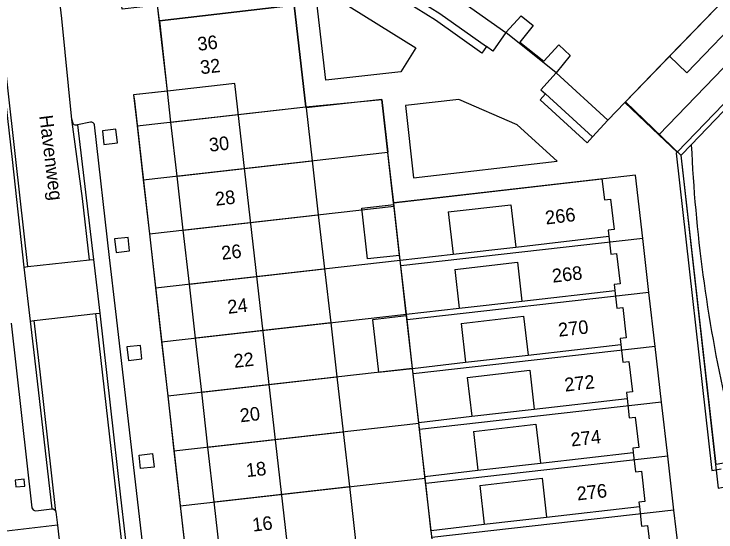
# Model space of a CAD drawing. Extents: x 194485 to 197793, y 468269 to 470822.
# Drawn here: x 194929.3 to 194991.2, y 469505.8 to 469551.5 of the extents above; entities that cross this region are included whole.
import ezdxf

# ---------------------------------------------------------------- set-up
doc = ezdxf.new("R2010")
doc.units = 0
for name, color, linetype in [('BGT begrenzing pand op maaiveld onder overbouw', 7, 'Continuous'), ('BGT grensvlak gebouwinstallatie plus 1', 7, 'Continuous'), ('BGT grensvlak onbegroeid terreindeel', 7, 'Continuous'), ('BGT grensvlak pand deel overbouw', 7, 'Continuous'), ('BGT grensvlak pand min 1', 7, 'Continuous'), ('BGT grensvlak pand op maaiveld', 7, 'Continuous'), ('BGT grensvlak pand op maaiveld LR', 7, 'Continuous'), ('BGT grensvlak scheiding', 7, 'Continuous'), ('BGT grensvlak wegdeel', 7, 'Continuous'), ('BGT lijnelement scheiding muur', 7, 'Continuous'), ('BGT tekst huisnummerreeks', 7, 'Continuous'), ('BGT tekst huisnummerreeks min 1', 7, 'Continuous'), ('BGT tekst openbare ruimte label weg', 7, 'Continuous'), ('GEM grensvlak WOZ_BRK percelen', 7, 'Continuous')]:
    doc.layers.add(name, color=color, linetype=linetype)

msp = doc.modelspace()

# ---------------------------------------------------------------- linework, layer by layer
at = {"layer": 'BGT begrenzing pand op maaiveld onder overbouw'}
msp.add_line((194987.109, 469547.829), (194992.078, 469552.978), dxfattribs=at)
msp.add_lwpolyline([(194972.663, 469549.909), (194974.005, 469551.384), (194975.072, 469550.524), (194973.905, 469549.076), (194976.016, 469547.376), (194977.329, 469548.818), (194978.342, 469547.895), (194977.091, 469546.343)], dxfattribs=at)
at = {"layer": 'BGT grensvlak gebouwinstallatie plus 1'}
for p, q in [((194959.954, 469534.412), (194962.773, 469534.723)), ((194960.447, 469529.925), (194959.954, 469534.412)), ((194963.286, 469530.238), (194960.447, 469529.925)), ((194963.896, 469524.895), (194960.909, 469524.553)), ((194960.909, 469524.553), (194961.439, 469519.927)), ((194961.439, 469519.927), (194964.426, 469520.269))]:
    msp.add_line(p, q, dxfattribs=at)
at = {"layer": 'BGT grensvlak onbegroeid terreindeel'}
msp.add_line((194980.312, 469540.703), (194976.144, 469544.5), dxfattribs=at)
msp.add_lwpolyline([(194962.56, 469554.267), (194966.831, 469551.598), (194970.958, 469548.667)], dxfattribs=at)
at = {"layer": 'BGT grensvlak pand deel overbouw'}
msp.add_line((194977.091, 469546.343), (194972.663, 469549.909), dxfattribs=at)
msp.add_lwpolyline([(194992.415, 469553.349), (194993.948, 469551.885), (194988.626, 469546.362), (194987.109, 469547.829)], dxfattribs=at)
at = {"layer": 'BGT grensvlak pand min 1'}
for points in [[(195136.748, 469494.684), (194989.988, 469465.668), (194991.149, 469459.781), (194987.304, 469459.017), (194987.908, 469455.979), (194958.837, 469450.201), (194954.733, 469470.846), (194957.233, 469471.136), (194948.757, 469545.418), (194942.798, 469544.743), (194941.933, 469552.333), (194938.82, 469551.976), (194935.239, 469583.018)], [(194992.078, 469552.978), (194983.207, 469543.786), (194988.084, 469539.079), (194991.402, 469509.689), (195033.444, 469518.043), (195038.067, 469534.581), (195024.346, 469538.411), (195028.4, 469552.907), (195043.72, 469548.616), (195044.259, 469550.568), (195051.101, 469548.618), (195057.258, 469546.789), (195062.48, 469545.169), (195068.699, 469543.142), (195074.87, 469540.905), (195079.968, 469538.994), (195086.152, 469536.574), (195092.257, 469534.001), (195097.233, 469531.758)]]:
    msp.add_lwpolyline(points, dxfattribs=at)
at = {"layer": 'BGT grensvlak pand op maaiveld'}
for p, q in [((194967.941, 469553.263), (194972.663, 469549.909)), ((194942.8, 469544.724), (194942.093, 469550.932)), ((194983.154, 469543.731), (194987.109, 469547.829)), ((194977.091, 469546.343), (194981.659, 469542.182)), ((194943.109, 469542.014), (194942.8, 469544.724)), ((194955.027, 469543.363), (194955.038, 469543.265)), ((194955.038, 469543.265), (194955.571, 469538.594)), ((194981.659, 469542.182), (194983.154, 469543.731)), ((194943.653, 469537.245), (194943.109, 469542.014)), ((194955.571, 469538.594), (194956.116, 469533.825)), ((194944.196, 469532.476), (194943.653, 469537.245)), ((194962.773, 469534.723), (194962.756, 469534.874)), ((194963.286, 469530.238), (194962.773, 469534.723)), ((194967.579, 469534.07), (194973.102, 469534.706)), ((194973.102, 469534.706), (194973.528, 469530.98)), ((194967.579, 469534.07), (194968.007, 469530.345)), ((194956.116, 469533.825), (194956.661, 469529.056)), ((194944.74, 469527.707), (194944.196, 469532.476)), ((194968.007, 469530.345), (194973.528, 469530.98)), ((194963.335, 469529.807), (194963.286, 469530.238)), ((194963.88, 469525.038), (194963.335, 469529.807)), ((194968.162, 469529.003), (194973.681, 469529.639)), ((194973.681, 469529.639), (194974.073, 469526.211)), ((194956.661, 469529.056), (194957.206, 469524.287)), ((194968.162, 469529.003), (194968.556, 469525.576)), ((194945.284, 469522.938), (194944.74, 469527.707)), ((194968.556, 469525.576), (194974.073, 469526.211)), ((194963.896, 469524.895), (194963.88, 469525.038)), ((194964.426, 469520.269), (194963.896, 469524.895)), ((194968.71, 469524.235), (194974.227, 469524.87)), ((194974.227, 469524.87), (194974.619, 469521.442)), ((194957.206, 469524.287), (194957.75, 469519.518)), ((194968.71, 469524.235), (194969.105, 469520.808)), ((194945.827, 469518.168), (194945.284, 469522.938)), ((194969.105, 469520.808), (194974.619, 469521.442)), ((194964.971, 469515.5), (194964.426, 469520.269)), ((194969.259, 469519.466), (194974.772, 469520.101)), ((194974.772, 469520.101), (194975.164, 469516.673)), ((194957.75, 469519.518), (194958.304, 469514.674)), ((194969.259, 469519.466), (194969.654, 469516.039)), ((194946.379, 469513.325), (194945.827, 469518.168)), ((194969.654, 469516.039), (194975.164, 469516.673)), ((194965.516, 469510.731), (194964.971, 469515.5)), ((194969.808, 469514.698), (194975.317, 469515.332)), ((194975.317, 469515.332), (194975.709, 469511.904)), ((194958.304, 469514.674), (194958.857, 469509.831)), ((194969.808, 469514.698), (194970.202, 469511.271)), ((194946.931, 469508.481), (194946.379, 469513.325)), ((194970.202, 469511.271), (194975.709, 469511.904)), ((194966.061, 469505.962), (194965.516, 469510.731)), ((194970.357, 469509.929), (194975.862, 469510.563)), ((194975.862, 469510.563), (194976.254, 469507.135)), ((194958.857, 469509.831), (194959.402, 469505.062)), ((194970.357, 469509.929), (194970.751, 469506.502)), ((194947.475, 469503.712), (194946.931, 469508.481)), ((194970.751, 469506.502), (194976.254, 469507.135)), ((194966.606, 469501.193), (194966.061, 469505.962))]:
    msp.add_line(p, q, dxfattribs=at)
for points in [[(194942.093, 469550.932), (194953.991, 469552.32), (194955.027, 469543.363)], [(194962.756, 469534.874), (194981.116, 469536.987), (194981.355, 469535.138), (194981.902, 469535.199), (194982.201, 469532.517), (194981.674, 469532.458), (194981.734, 469531.924)], [(194981.734, 469531.924), (194981.909, 469530.351), (194982.436, 469530.41), (194982.739, 469527.726), (194982.212, 469527.667), (194982.271, 469527.154)], [(194982.271, 469527.154), (194982.451, 469525.583), (194982.978, 469525.642), (194983.278, 469522.962), (194982.751, 469522.902), (194982.81, 469522.385)], [(194982.81, 469522.385), (194982.99, 469520.818), (194983.517, 469520.878), (194983.823, 469518.195), (194983.296, 469518.135), (194983.355, 469517.616)], [(194983.355, 469517.616), (194983.549, 469515.907), (194984.076, 469515.967), (194984.379, 469513.288), (194983.852, 469513.228), (194983.896, 469512.846)], [(194983.896, 469512.846), (194984.092, 469511.135), (194984.619, 469511.195), (194984.923, 469508.51), (194984.396, 469508.45), (194984.437, 469508.077)], [(194984.437, 469508.077), (194984.626, 469506.347), (194985.152, 469506.409), (194985.467, 469503.726), (194984.941, 469503.664), (194984.98, 469503.308)]]:
    msp.add_lwpolyline(points, dxfattribs=at)
at = {"layer": 'BGT grensvlak pand op maaiveld LR'}
for p, q in [((194943.109, 469542.014), (194955.027, 469543.363)), ((194943.653, 469537.245), (194955.571, 469538.594)), ((194944.196, 469532.476), (194956.116, 469533.825)), ((194973.528, 469530.98), (194981.734, 469531.924)), ((194963.335, 469529.807), (194968.007, 469530.345)), ((194944.74, 469527.707), (194956.661, 469529.056)), ((194974.073, 469526.211), (194982.271, 469527.154)), ((194963.88, 469525.038), (194968.556, 469525.576)), ((194957.206, 469524.287), (194945.284, 469522.938)), ((194974.619, 469521.442), (194982.81, 469522.385)), ((194964.426, 469520.269), (194969.105, 469520.808)), ((194945.827, 469518.168), (194957.75, 469519.518)), ((194975.164, 469516.673), (194983.355, 469517.616)), ((194964.971, 469515.5), (194969.654, 469516.039)), ((194946.379, 469513.325), (194958.304, 469514.674)), ((194975.709, 469511.904), (194983.896, 469512.846)), ((194965.516, 469510.731), (194970.202, 469511.271)), ((194946.931, 469508.481), (194958.857, 469509.831)), ((194976.254, 469507.135), (194984.437, 469508.077)), ((194966.061, 469505.962), (194970.751, 469506.502))]:
    msp.add_line(p, q, dxfattribs=at)
at = {"layer": 'BGT grensvlak scheiding'}
msp.add_line((194996.67, 469548.615), (194987.781, 469539.347), dxfattribs=at)
for points in [[(194989.019, 469539.985), (194997.435, 469548.806), (194997.141, 469549.094), (194996.67, 469548.615)], [(194993.03, 469512.107), (194991.222, 469511.769), (194988.139, 469539.08), (194989.019, 469539.985)], [(194987.781, 469539.347), (194987.672, 469539.261), (194990.825, 469511.259), (194991.66, 469511.405)]]:
    msp.add_lwpolyline(points, dxfattribs=at)
at = {"layer": 'BGT grensvlak wegdeel'}
for p, q in [((194942.093, 469550.932), (194941.931, 469552.333)), ((194986.17, 469540.873), (194995.053, 469550.149)), ((194986.17, 469540.873), (194983.154, 469543.731)), ((194934.37, 469542.235), (194934.427, 469542.005)), ((194934.427, 469542.005), (194934.45, 469541.923)), ((194936.03, 469541.997), (194934.876, 469541.778)), ((194980.312, 469540.703), (194981.659, 469542.182)), ((194934.72, 469541.754), (194934.781, 469541.76)), ((194934.781, 469541.76), (194934.876, 469541.778)), ((194934.876, 469541.778), (194936.28, 469529.887)), ((194937.708, 469530.045), (194936.359, 469541.755)), ((194987.781, 469539.347), (194986.17, 469540.873)), ((194930.496, 469529.249), (194935.936, 469529.849)), ((194935.936, 469529.849), (194936.28, 469529.887)), ((194936.28, 469529.887), (194936.834, 469525.135)), ((194938.256, 469525.296), (194937.708, 469530.045)), ((194930.135, 469529.209), (194930.496, 469529.249)), ((194930.135, 469529.209), (194930.699, 469524.44)), ((194931.047, 469524.48), (194936.494, 469525.096)), ((194936.494, 469525.096), (194936.834, 469525.135)), ((194929.012, 469524.249), (194930.852, 469507.969)), ((194930.699, 469524.44), (194931.047, 469524.48)), ((194931.184, 469507.703), (194932.592, 469507.856)), ((194932.592, 469507.856), (194932.618, 469507.859)), ((194932.618, 469507.859), (194932.634, 469507.86)), ((194932.634, 469507.86), (194932.654, 469507.862)), ((194932.654, 469507.862), (194932.725, 469507.855)), ((194932.725, 469507.855), (194932.823, 469507.815)), ((194932.823, 469507.815), (194932.884, 469507.764)), ((194932.884, 469507.764), (194932.932, 469507.692)), ((194932.932, 469507.692), (194932.955, 469507.625)), ((194932.955, 469507.625), (194932.96, 469507.594)), ((194933.112, 469506.413), (194928.109, 469505.832)), ((194933.112, 469506.413), (194933.803, 469500.455))]:
    msp.add_line(p, q, dxfattribs=at)
for points in [[(194930.496, 469529.249), (194929.436, 469538.705), (194927.862, 469552.418), (194926.216, 469567.036), (194926.149, 469567.309)], [(194925.913, 469566.989), (194927.524, 469552.404), (194929.093, 469538.696), (194930.135, 469529.209)], [(194934.37, 469542.235), (194933.484, 469551.142), (194932.767, 469557.399)], [(194970.958, 469548.667), (194970.552, 469548.096), (194966.442, 469551.016), (194962.189, 469553.674), (194962.56, 469554.267)], [(194963.4, 469546.438), (194956.768, 469545.717), (194955.977, 469552.56), (194957.946, 469552.788), (194964.722, 469548.553), (194963.4, 469546.438)], [(194972.663, 469549.909), (194971.505, 469548.278), (194970.958, 469548.667)], [(194977.091, 469546.343), (194975.744, 469544.864), (194976.144, 469544.5)], [(194942.8, 469544.724), (194939.825, 469544.405), (194939.886, 469543.859), (194948.292, 469469.627), (194951.273, 469469.965), (194952.284, 469470.079)], [(194976.144, 469544.5), (194975.673, 469543.982), (194979.841, 469540.186), (194980.312, 469540.703)], [(194963.796, 469543.471), (194964.518, 469537.09), (194977.184, 469538.548), (194973.653, 469541.765), (194968.506, 469544.004), (194963.796, 469543.471)], [(194935.936, 469529.849), (194935.303, 469535.252), (194934.37, 469542.235)], [(194937.064, 469541.235), (194937.199, 469540.043), (194938.392, 469540.178), (194938.257, 469541.37), (194937.064, 469541.235)], [(194938.144, 469531.696), (194938.279, 469530.504), (194939.472, 469530.639), (194939.337, 469531.831), (194938.144, 469531.696)], [(194946.546, 469453.293), (194944.778, 469468.253), (194941.389, 469498.021), (194938.256, 469525.296)], [(194944.79, 469452.543), (194944.734, 469452.757), (194942.605, 469471.203), (194936.494, 469525.096)], [(194936.834, 469525.135), (194938.66, 469508.895), (194940.18, 469495.711), (194942.923, 469471.215), (194943.743, 469464.369), (194945.037, 469452.838)], [(194930.699, 469524.44), (194931.238, 469519.891), (194932.592, 469507.856)], [(194932.955, 469507.625), (194931.571, 469519.951), (194931.047, 469524.48)], [(194939.225, 469522.157), (194939.36, 469520.965), (194940.552, 469521.1), (194940.417, 469522.292), (194939.225, 469522.157)], [(194940.304, 469512.618), (194941.497, 469512.753), (194941.632, 469511.56), (194940.439, 469511.425), (194940.304, 469512.618)], [(194929.362, 469510.397), (194929.428, 469509.814), (194930.235, 469509.854), (194930.165, 469510.474), (194929.362, 469510.397)], [(194932.96, 469507.594), (194933.112, 469506.414), (194933.112, 469506.413)]]:
    msp.add_lwpolyline(points, dxfattribs=at)
for centre, radius, start, end in [((194934.721, 469542.056), 0.302, 206.06994, 235.45727), ((194936.097, 469541.744), 0.262, 2.42298, 104.90342), ((194934.71, 469542.02), 0.266, 233.14387, 272.22486), ((195121.218, 469546.059), 132.339, 182.63072, 192.60857), ((194931.147, 469507.997), 0.296, 185.37486, 277.22139)]:
    msp.add_arc(centre, radius, start, end, dxfattribs=at)
at = {"layer": 'BGT lijnelement scheiding muur'}
msp.add_lwpolyline([(194962.756, 469534.874), (194961.724, 469543.993), (194955.038, 469543.265)], dxfattribs=at)
at = {"layer": 'GEM grensvlak WOZ_BRK percelen'}
for p, q in [((194940.133, 469541.677), (194955.027, 469543.363)), ((194940.133, 469541.677), (194940.673, 469536.908)), ((194940.673, 469536.908), (194962.254, 469539.35)), ((194962.765, 469534.875), (194962.254, 469539.35)), ((194940.673, 469536.908), (194941.213, 469532.138)), ((194941.213, 469532.138), (194962.798, 469534.581)), ((194962.798, 469534.581), (194962.765, 469534.875)), ((194963.343, 469529.812), (194962.798, 469534.581)), ((194941.213, 469532.138), (194941.753, 469527.369)), ((194984.737, 469531.744), (194963.398, 469529.329)), ((194985.284, 469526.975), (194984.737, 469531.744)), ((194941.753, 469527.369), (194963.343, 469529.812)), ((194963.398, 469529.329), (194963.343, 469529.812)), ((194963.887, 469525.043), (194963.398, 469529.329)), ((194941.753, 469527.369), (194942.294, 469522.6)), ((194985.284, 469526.975), (194963.942, 469524.56)), ((194985.83, 469522.207), (194985.284, 469526.975)), ((194942.294, 469522.6), (194963.887, 469525.043)), ((194963.942, 469524.56), (194963.887, 469525.043)), ((194964.432, 469520.275), (194963.942, 469524.56)), ((194942.294, 469522.6), (194942.834, 469517.829)), ((194985.83, 469522.207), (194964.487, 469519.79)), ((194986.394, 469517.29), (194985.83, 469522.207)), ((194942.834, 469517.829), (194964.432, 469520.275)), ((194964.487, 469519.79), (194964.432, 469520.275)), ((194964.985, 469515.43), (194964.487, 469519.79)), ((194942.834, 469517.829), (194943.382, 469512.986)), ((194986.394, 469517.29), (194965.048, 469514.872)), ((194986.941, 469512.52), (194986.394, 469517.29)), ((194943.382, 469512.986), (194964.985, 469515.43)), ((194965.048, 469514.872), (194964.985, 469515.43)), ((194965.537, 469510.587), (194965.048, 469514.872)), ((194943.382, 469512.986), (194943.931, 469508.141)), ((194986.941, 469512.52), (194965.593, 469510.103)), ((194987.488, 469507.752), (194986.941, 469512.52)), ((194943.931, 469508.141), (194965.537, 469510.587)), ((194965.593, 469510.103), (194965.537, 469510.587)), ((194966.082, 469505.818), (194965.593, 469510.103)), ((194943.931, 469508.141), (194944.471, 469503.372)), ((194987.488, 469507.752), (194966.137, 469505.335)), ((194988.035, 469502.982), (194987.488, 469507.752))]:
    msp.add_line(p, q, dxfattribs=at)
for points in [[(194955.027, 469543.363), (194953.991, 469552.32), (194942.09, 469550.932), (194942.791, 469544.742), (194939.824, 469544.406), (194940.133, 469541.677)], [(194955.027, 469543.363), (194961.724, 469543.993), (194962.254, 469539.35)], [(194984.737, 469531.744), (194984.096, 469537.329), (194962.765, 469534.875)]]:
    msp.add_lwpolyline(points, dxfattribs=at)

# ---------------------------------------------------------------- texts
at = {"layer": 'BGT tekst huisnummerreeks'}
for s, rotation, p in [('32', 6.5, (194945.761, 469546.229)), ('30', 6.5, (194946.537, 469539.386)), ('28', 6.5, (194947.078, 469534.616)), ('266', 6.9, (194976.204, 469532.959)), ('26', 6.5, (194947.622, 469529.848)), ('268', 6.4, (194976.8, 469527.829)), ('24', 6.5, (194948.168, 469525.079)), ('270', 6.4, (194977.343, 469523.059)), ('22', 6.5, (194948.716, 469520.308)), ('272', 6.5, (194977.898, 469518.211)), ('20', 6.5, (194949.259, 469515.502)), ('274', 6.5, (194978.446, 469513.367)), ('18', 6.5, (194949.808, 469510.659)), ('276', 6.4, (194978.981, 469508.604)), ('16', 6.5, (194950.357, 469505.853))]:
    msp.add_text(s, height=1.2, rotation=rotation, dxfattribs=at).set_placement(p)
at = {"layer": 'BGT tekst huisnummerreeks min 1'}
msp.add_text('36', height=1.2, rotation=6.5, dxfattribs=at).set_placement((194945.52, 469548.294))
at = {"layer": 'BGT tekst openbare ruimte label weg'}
msp.add_text('Havenweg', height=1.2, rotation=277, dxfattribs=at).set_placement((194931.493, 469542.556))

doc.saveas('drawing.dxf')
